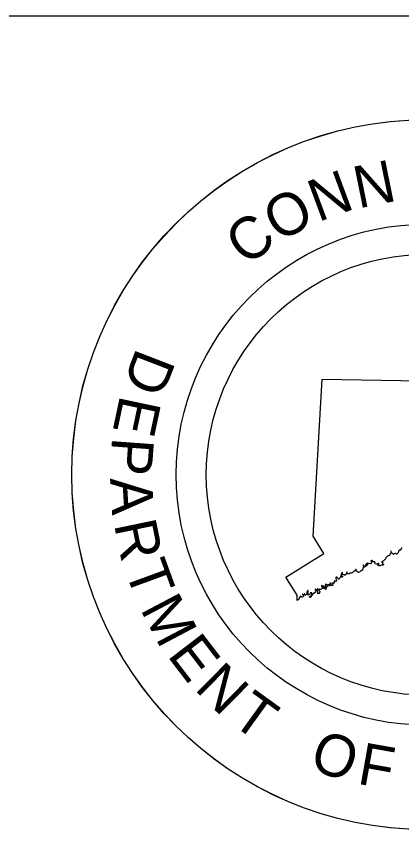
# Model space of a CAD drawing. Extents: x 0 to 2011, y -71 to 1183.
# Drawn here: x 616.27 to 630.97, y 28.04 to 59.03 of the extents above; entities that cross this region are included whole.
import ezdxf

# ---------------------------------------------------------------- set-up
doc = ezdxf.new("R2010")
doc.units = 0
doc.layers.add('CT_Graphics', color=7, linetype='Continuous')
doc.layers.add('CT_Title_Block_Linework', color=7, linetype='Continuous')

msp = doc.modelspace()

# ---------------------------------------------------------------- linework, layer by layer
at = {"layer": 'CT_Graphics'}
for p, q in [((627.585, 39.216), (627.936, 45.204)), ((627.585, 39.216), (627.936, 45.204)), ((627.936, 45.204), (631.869, 45.141)), ((627.936, 45.204), (631.869, 45.141)), ((627.996, 38.566), (627.585, 39.216)), ((627.996, 38.566), (627.585, 39.216)), ((626.55, 37.661), (627.996, 38.566)), ((626.55, 37.661), (627.996, 38.566)), ((626.985, 36.968), (626.55, 37.661)), ((626.985, 36.968), (626.55, 37.661))]:
    msp.add_line(p, q, dxfattribs=at)
msp.add_lwpolyline([(626.979, 36.765), (626.985, 36.968)], dxfattribs=at)
msp.add_lwpolyline([(626.979, 36.765), (626.985, 36.968)], dxfattribs=at)
for centre, major_axis in [((631.913, 41.564), (0, 13.525)), ((631.915, 41.561), (0, 13.525)), ((631.913, 41.564), (0, 9.547)), ((631.915, 41.561), (0, 8.399))]:
    msp.add_ellipse(centre, major_axis=major_axis, ratio=0.99999, dxfattribs=at)
for points in [[(630.961, 38.787), (630.954, 38.759), (630.93, 38.73), (630.93, 38.703), (630.902, 38.687), (630.875, 38.681), (630.838, 38.623), (630.821, 38.569), (630.793, 38.544), (630.765, 38.539), (630.736, 38.557), (630.682, 38.547), (630.653, 38.526), (630.625, 38.542), (630.57, 38.627), (630.564, 38.657), (630.548, 38.63), (630.569, 38.603), (630.554, 38.572), (630.529, 38.545), (630.494, 38.488), (630.438, 38.466), (630.41, 38.447), (630.382, 38.418), (630.301, 38.303), (630.244, 38.268)], [(630.961, 38.787), (630.954, 38.759), (630.93, 38.73), (630.93, 38.703), (630.902, 38.687), (630.875, 38.681), (630.838, 38.623), (630.821, 38.569), (630.793, 38.544), (630.765, 38.539), (630.736, 38.557), (630.682, 38.547), (630.653, 38.526), (630.625, 38.542), (630.57, 38.627), (630.564, 38.657), (630.548, 38.63), (630.569, 38.603), (630.554, 38.572), (630.529, 38.545), (630.494, 38.488), (630.438, 38.466), (630.41, 38.447), (630.382, 38.418), (630.301, 38.303), (630.244, 38.268)], [(630.209, 38.265), (630.233, 38.238), (630.201, 38.235), (630.23, 38.224), (630.233, 38.165), (630.261, 38.15), (630.273, 38.122), (630.245, 38.122), (630.19, 38.111), (630.132, 38.087), (630.077, 38.098), (630.048, 38.117), (630.077, 38.117), (630.089, 38.144), (630.081, 38.173), (630.053, 38.184), (630.024, 38.158), (629.999, 38.155), (629.941, 38.193), (629.949, 38.22), (629.927, 38.248), (629.9, 38.236), (629.871, 38.252), (629.855, 38.279), (629.823, 38.297), (629.796, 38.298), (629.796, 38.271), (629.814, 38.244), (629.812, 38.214), (629.795, 38.181), (629.713, 38.173), (629.656, 38.136), (629.618, 38.079), (629.621, 38.111), (629.647, 38.139), (629.67, 38.168), (629.677, 38.198), (629.621, 38.163), (629.578, 38.104), (629.576, 38.077), (629.559, 38.048), (629.53, 38.042), (629.518, 38.098), (629.492, 38.125), (629.508, 38.098), (629.51, 38.071), (629.506, 38.042), (629.473, 37.956), (629.47, 37.926), (629.441, 37.908), (629.412, 37.9), (629.358, 37.852), (629.274, 37.857), (629.25, 37.886), (629.22, 37.899), (629.22, 37.929), (629.248, 37.953), (629.221, 37.945), (629.194, 37.916), (629.166, 37.902), (629.116, 37.849), (629.087, 37.84), (629.06, 37.816), (629.005, 37.811), (628.976, 37.802), (628.949, 37.781), (628.919, 37.792), (628.892, 37.782)], [(630.209, 38.265), (630.233, 38.238), (630.201, 38.235), (630.23, 38.224), (630.233, 38.165), (630.261, 38.15), (630.273, 38.122), (630.245, 38.122), (630.19, 38.111), (630.132, 38.087), (630.077, 38.098), (630.048, 38.117), (630.077, 38.117), (630.089, 38.144), (630.081, 38.173), (630.053, 38.184), (630.024, 38.158), (629.999, 38.155), (629.941, 38.193), (629.949, 38.22), (629.927, 38.248), (629.9, 38.236), (629.871, 38.252), (629.855, 38.279), (629.823, 38.297), (629.796, 38.298), (629.796, 38.271), (629.814, 38.244), (629.812, 38.214), (629.795, 38.181), (629.713, 38.173), (629.656, 38.136), (629.618, 38.079), (629.621, 38.111), (629.647, 38.139), (629.67, 38.168), (629.677, 38.198), (629.621, 38.163), (629.578, 38.104), (629.576, 38.077), (629.559, 38.048), (629.53, 38.042), (629.518, 38.098), (629.492, 38.125), (629.508, 38.098), (629.51, 38.071), (629.506, 38.042), (629.473, 37.956), (629.47, 37.926), (629.441, 37.908), (629.412, 37.9), (629.358, 37.852), (629.274, 37.857), (629.25, 37.886), (629.22, 37.899), (629.22, 37.929), (629.248, 37.953), (629.221, 37.945), (629.194, 37.916), (629.166, 37.902), (629.116, 37.849), (629.087, 37.84), (629.06, 37.816), (629.005, 37.811), (628.976, 37.802), (628.949, 37.781), (628.919, 37.792), (628.892, 37.782)], [(628.895, 37.786), (628.866, 37.797), (628.89, 37.825), (628.882, 37.854), (628.857, 37.829), (628.852, 37.771), (628.823, 37.743), (628.794, 37.73), (628.766, 37.746), (628.766, 37.773), (628.739, 37.752), (628.71, 37.762), (628.71, 37.817), (628.705, 37.845), (628.68, 37.816), (628.656, 37.73), (628.675, 37.701), (628.704, 37.692), (628.713, 37.663), (628.684, 37.663), (628.661, 37.69), (628.634, 37.69), (628.632, 37.66), (628.579, 37.602), (628.57, 37.575), (628.543, 37.601), (628.498, 37.658), (628.471, 37.663), (628.455, 37.633), (628.465, 37.577), (628.477, 37.55), (628.458, 37.491), (628.428, 37.504), (628.404, 37.529), (628.39, 37.446), (628.375, 37.418), (628.355, 37.445), (628.331, 37.414), (628.328, 37.386), (628.337, 37.357), (628.312, 37.333), (628.283, 37.346), (628.254, 37.459), (628.258, 37.43), (628.251, 37.373), (628.226, 37.343), (628.199, 37.316), (628.202, 37.343), (628.226, 37.371), (628.226, 37.402), (628.199, 37.376), (628.17, 37.367), (628.141, 37.368), (628.116, 37.34), (628.13, 37.309), (628.1, 37.293), (628.082, 37.265), (628.109, 37.265), (628.087, 37.236), (628.079, 37.187)], [(628.895, 37.786), (628.866, 37.797), (628.89, 37.825), (628.882, 37.854), (628.857, 37.829), (628.852, 37.771), (628.823, 37.743), (628.794, 37.73), (628.766, 37.746), (628.766, 37.773), (628.739, 37.752), (628.71, 37.762), (628.71, 37.817), (628.705, 37.845), (628.68, 37.816), (628.656, 37.73), (628.675, 37.701), (628.704, 37.692), (628.713, 37.663), (628.684, 37.663), (628.661, 37.69), (628.634, 37.69), (628.632, 37.66), (628.579, 37.602), (628.57, 37.575), (628.543, 37.601), (628.498, 37.658), (628.471, 37.663), (628.455, 37.633), (628.465, 37.577), (628.477, 37.55), (628.458, 37.491), (628.428, 37.504), (628.404, 37.529), (628.39, 37.446), (628.375, 37.418), (628.355, 37.445), (628.331, 37.414), (628.328, 37.386), (628.337, 37.357), (628.312, 37.333), (628.283, 37.346), (628.254, 37.459), (628.258, 37.43), (628.251, 37.373), (628.226, 37.343), (628.199, 37.316), (628.202, 37.343), (628.226, 37.371), (628.226, 37.402), (628.199, 37.376), (628.17, 37.367), (628.141, 37.368), (628.116, 37.34), (628.13, 37.309), (628.1, 37.293), (628.082, 37.265), (628.109, 37.265), (628.087, 37.236), (628.079, 37.187)], [(627.678, 37.217), (627.668, 37.188), (627.687, 37.133), (627.681, 37.104), (627.663, 37.075), (627.635, 37.08), (627.609, 37.024), (627.579, 37.018), (627.538, 36.959), (627.531, 36.929), (627.504, 36.902), (627.477, 36.892), (627.452, 36.892), (627.45, 36.919), (627.479, 36.922), (627.507, 36.946), (627.526, 36.973), (627.536, 37.002), (627.534, 37.059), (627.509, 37.056), (627.496, 37.083), (627.499, 37.056), (627.471, 37.031), (627.452, 37.002), (627.396, 36.978), (627.38, 37.005), (627.405, 37.034), (627.39, 37.09), (627.402, 37.147), (627.375, 37.137), (627.366, 37.107), (627.343, 37.078), (627.345, 37.05), (627.307, 36.989), (627.28, 36.972), (627.273, 37.027), (627.251, 36.999), (627.249, 36.97), (627.221, 36.975), (627.211, 37.002), (627.184, 37.007), (627.195, 36.98), (627.217, 36.953), (627.21, 36.924), (627.189, 36.894), (627.16, 36.91), (627.131, 36.903), (627.117, 36.932), (627.09, 36.916), (627.06, 36.859), (627.053, 36.828), (626.979, 36.765)], [(627.678, 37.217), (627.668, 37.188), (627.687, 37.133), (627.681, 37.104), (627.663, 37.075), (627.635, 37.08), (627.609, 37.024), (627.579, 37.018), (627.538, 36.959), (627.531, 36.929), (627.504, 36.902), (627.477, 36.892), (627.452, 36.892), (627.45, 36.919), (627.479, 36.922), (627.507, 36.946), (627.526, 36.973), (627.536, 37.002), (627.534, 37.059), (627.509, 37.056), (627.496, 37.083), (627.499, 37.056), (627.471, 37.031), (627.452, 37.002), (627.396, 36.978), (627.38, 37.005), (627.405, 37.034), (627.39, 37.09), (627.402, 37.147), (627.375, 37.137), (627.366, 37.107), (627.343, 37.078), (627.345, 37.05), (627.307, 36.989), (627.28, 36.972), (627.273, 37.027), (627.251, 36.999), (627.249, 36.97), (627.221, 36.975), (627.211, 37.002), (627.184, 37.007), (627.195, 36.98), (627.217, 36.953), (627.21, 36.924), (627.189, 36.894), (627.16, 36.91), (627.131, 36.903), (627.117, 36.932), (627.09, 36.916), (627.06, 36.859), (627.053, 36.828), (626.979, 36.765)], [(628.078, 37.174), (628.044, 37.26), (628.081, 37.405), (628.049, 37.32), (628.028, 37.293), (628.03, 37.265), (628.014, 37.236), (628.011, 37.209), (627.998, 37.236), (627.976, 37.265), (627.993, 37.293), (627.936, 37.332), (627.907, 37.336), (627.928, 37.281), (627.896, 37.195), (627.84, 37.191), (627.812, 37.214), (627.81, 37.185), (627.81, 37.158), (627.832, 37.129), (627.84, 37.102), (627.834, 37.072), (627.778, 37.024), (627.767, 37.053), (627.764, 37.11), (627.754, 37.14), (627.753, 37.166), (627.773, 37.195), (627.767, 37.223), (627.748, 37.193), (627.721, 37.171), (627.692, 37.169), (627.678, 37.209)], [(628.078, 37.174), (628.044, 37.26), (628.081, 37.405), (628.049, 37.32), (628.028, 37.293), (628.03, 37.265), (628.014, 37.236), (628.011, 37.209), (627.998, 37.236), (627.976, 37.265), (627.993, 37.293), (627.936, 37.332), (627.907, 37.336), (627.928, 37.281), (627.896, 37.195), (627.84, 37.191), (627.812, 37.214), (627.81, 37.185), (627.81, 37.158), (627.832, 37.129), (627.84, 37.102), (627.834, 37.072), (627.778, 37.024), (627.767, 37.053), (627.764, 37.11), (627.754, 37.14), (627.753, 37.166), (627.773, 37.195), (627.767, 37.223), (627.748, 37.193), (627.721, 37.171), (627.692, 37.169), (627.678, 37.209)]]:
    msp.add_spline(points, degree=3, dxfattribs=at)
at = {"layer": 'CT_Title_Block_Linework'}
msp.add_line((1270, 59.027), (0, 59.027), dxfattribs=at)

# ---------------------------------------------------------------- texts
at = {"layer": 'CT_Graphics'}
for s, rotation, p in [('N', 11.4758, (629.312, 51.699)), ('N', 20.3479, (627.779, 51.177)), ('O', 29.5691, (626.291, 50.39)), ('C', 37.9965, (625.057, 49.47)), ('D', 248.9249, (620.871, 46.438)), ('E', 257.9978, (620.24, 44.636)), ('P', 265.8361, (619.93, 43.015)), ('A', 273.4128, (619.844, 41.422)), ('R', 281.7094, (619.99, 39.682)), ('T', 290.1103, (620.393, 37.96)), ('M', 297.8049, (620.979, 36.45)), ('E', 307.5238, (621.999, 34.678)), ('N', 315.3621, (623.031, 33.39)), ('T', 324.2342, (624.398, 32.118)), ('O', 340.6959, (627.383, 30.376)), ('F', 349.9172, (629.234, 29.794))]:
    msp.add_text(s, height=1.6, rotation=rotation, dxfattribs=at).set_placement(p)

doc.saveas('drawing.dxf')
